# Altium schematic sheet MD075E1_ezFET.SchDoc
size 431 x 279 mm; Date: Not shown in title block; ApprovedBy: Not shown in title block; CheckedBy: Not shown in title block; Author: Not shown in title block; CompanyName: Not shown in title block; DrawnBy: Murugavel Raju; Engineer: Not shown in title block; Organization: Not shown in title block; Address1: Not shown in title block; Address2: Not shown in title block; Address3: Not shown in title block; Address4: Not shown in title block; DocumentNumber: 1; Revision: Use project parameter SCH_Rev; SheetNumber: 1; SheetTotal: 3; PageSetup: Record=PageOptions¦CenterHorizontal=True¦CenterVertical=True¦PrintScale=1.00¦XCorrection=1.00¦YCorrection=1.00¦PrintKind=0¦BorderSize=5000000¦LeftOffset=0¦BottomOffset=0¦Orientation=2¦PaperLength=1000¦PaperWidth=1000¦Scale=100¦PaperSource=15¦PrintQuality=600¦MediaType=1¦DitherType=10¦PaperKind=Letter¦PrintScaleMode=1
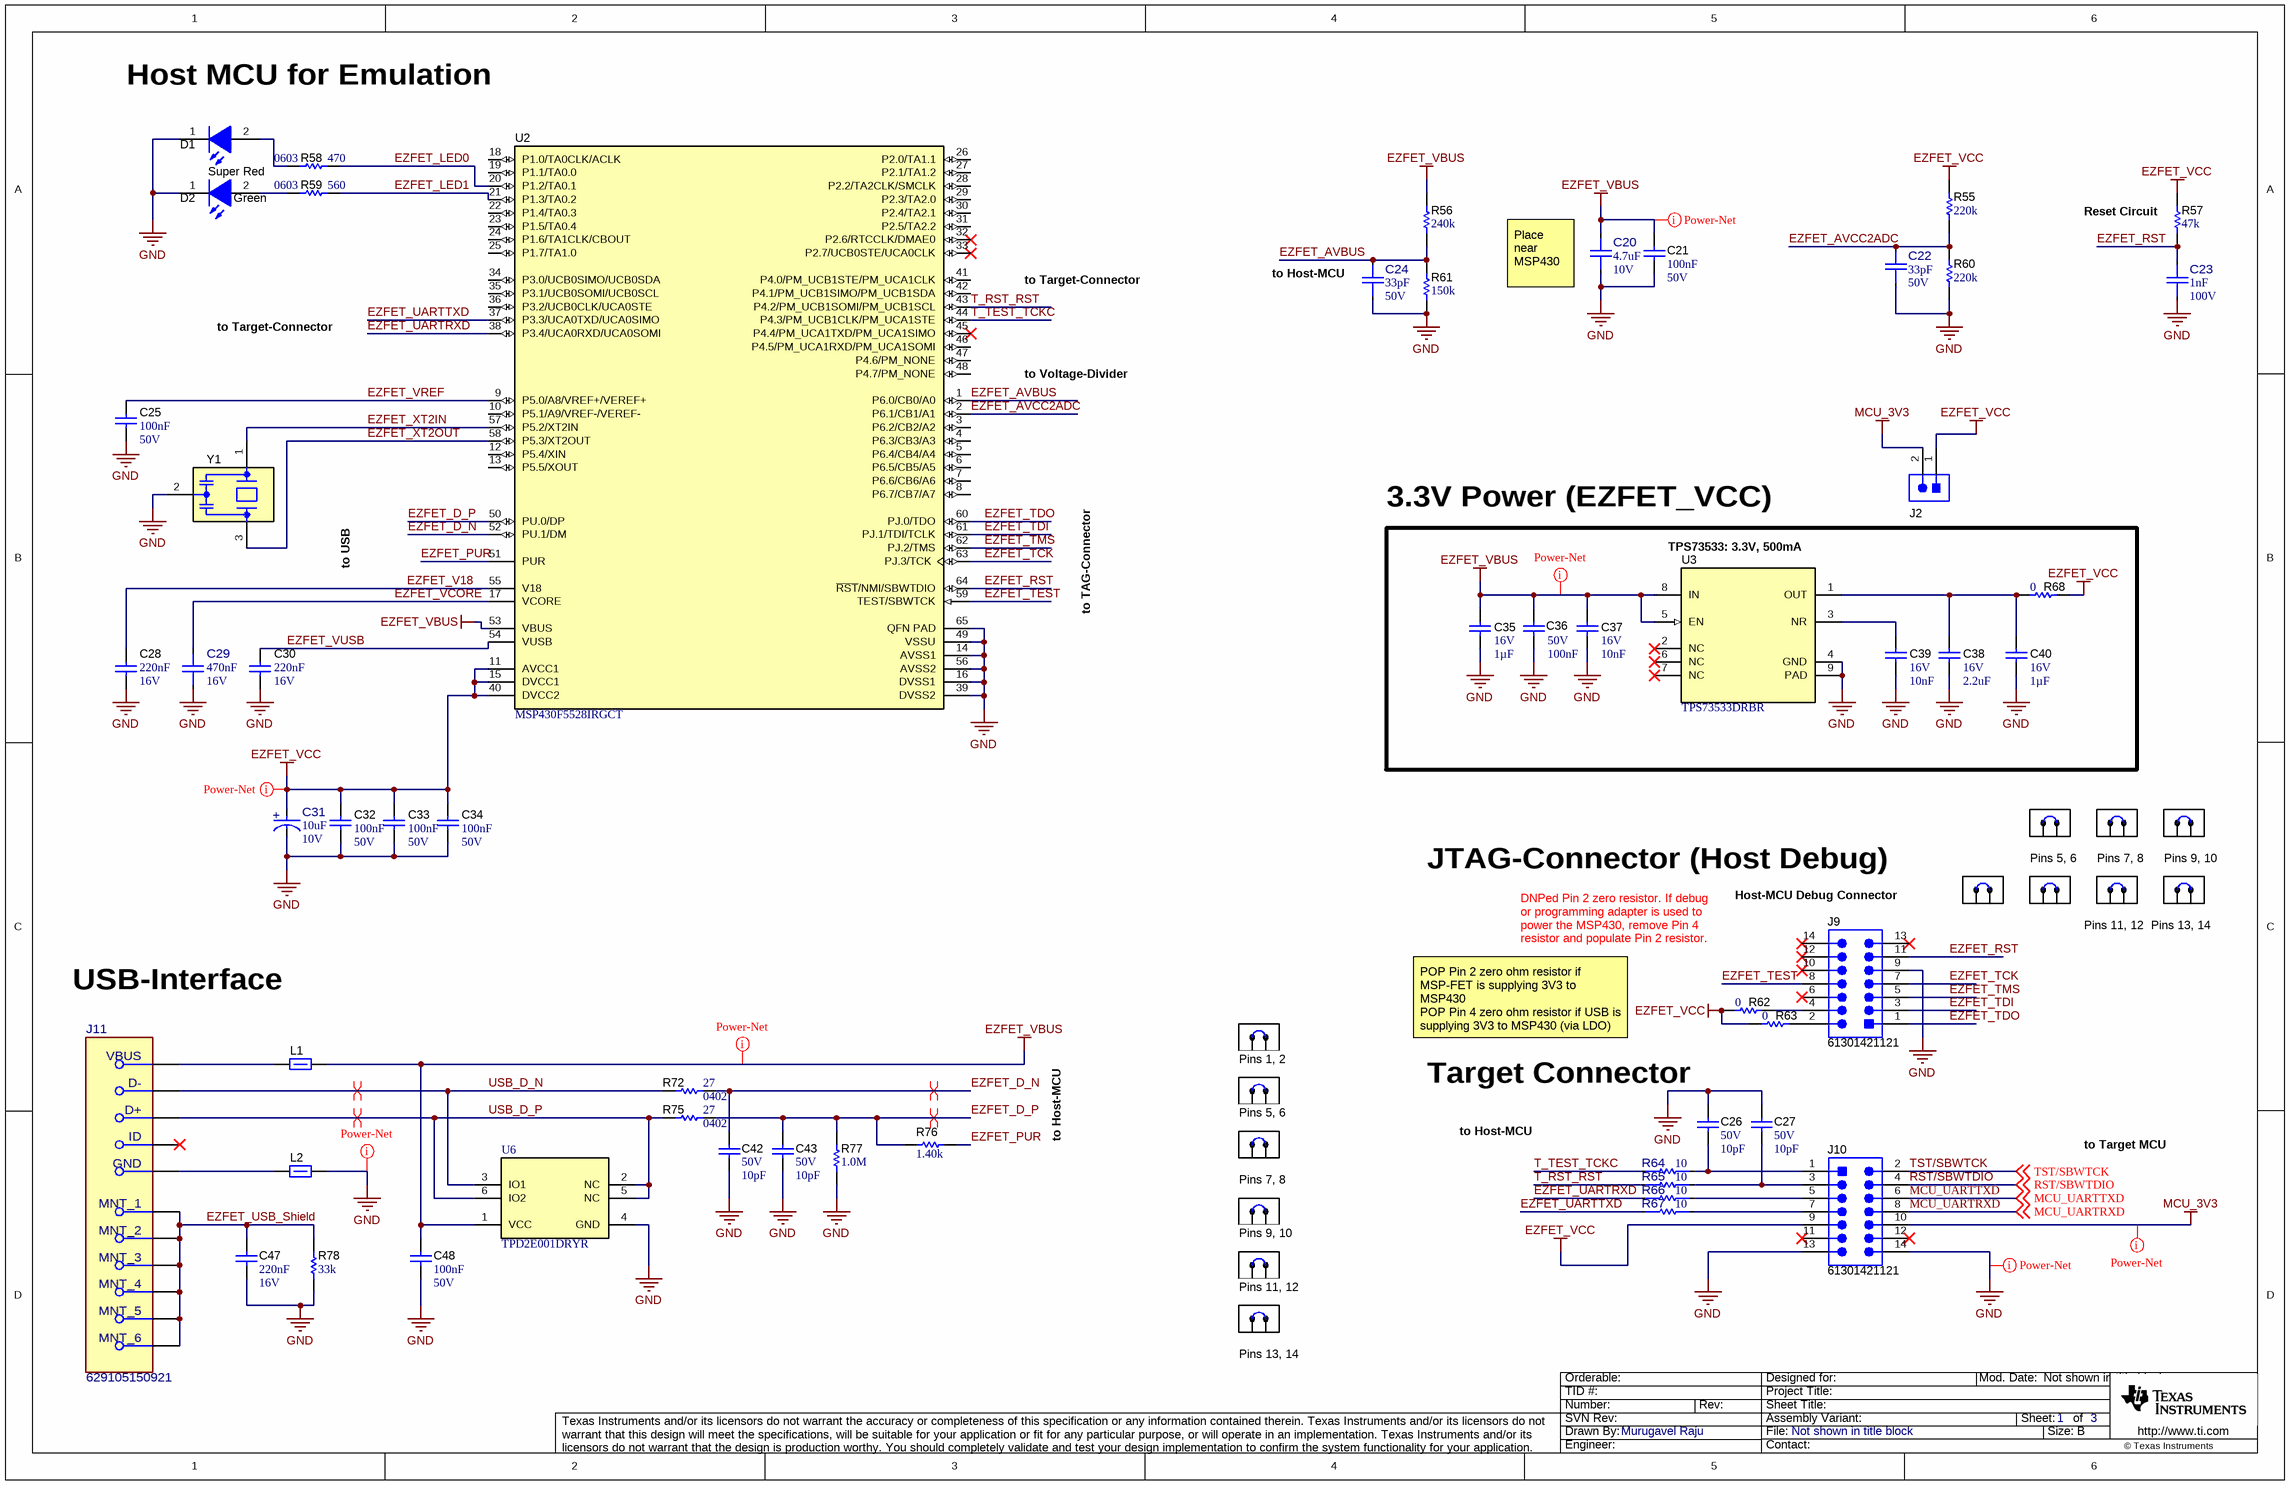
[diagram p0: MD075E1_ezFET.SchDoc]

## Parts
C20  ValueDisplayed: 4.7uF  VDC_V: 10V  [FP-885012106012_0603-MFG]  (hidden comment: 885012106012)
C21  Cap_F: 100nF  VDC_V: 50V  [0603]  (hidden comment: 885012206095)
C22  ValueDisplayed: 33pF  VDC_V: 50V  [FP-885012005058_0402-MFG]  (hidden comment: 885012005058)
C23  ValueDisplayed: 1nF  VDC_V: 100V  [FP-885012006085_0603-MFG]  (hidden comment: 885012006085)
C24  ValueDisplayed: 33pF  VDC_V: 50V  [FP-885012005058_0402-MFG]  (hidden comment: 885012005058)
C25  Cap_F: 100nF  VDC_V: 50V  [0603]  (hidden comment: 885012206095)
C26  VDC_V: 50V  ValueDisplayed: 10pF  [0402]  (hidden comment: 885012005055)
C27  VDC_V: 50V  ValueDisplayed: 10pF  [0402]  (hidden comment: 885012005055)
C28  Cap_F: 220nF  VDC_V: 16V  [0603L]  (hidden comment: 885012206048)
C29  VDC_V: 16V  Cap_F: 470nF  [FP-885012206050_0603-MFG]  (hidden comment: 885012206050)
C30  Cap_F: 220nF  VDC_V: 16V  [0603L]  (hidden comment: 885012206048)
C31  ValueDisplayed: 10uF  VDC_V: 10V  [FP-875105240001_SMT_CAP_4MM3_4MM3-MFG]  (hidden comment: 875105240001)
C32  Cap_F: 100nF  VDC_V: 50V  [0603]  (hidden comment: 885012206095)
C33  Cap_F: 100nF  VDC_V: 50V  [0603]  (hidden comment: 885012206095)
C34  Cap_F: 100nF  VDC_V: 50V  [0603]  (hidden comment: 885012206095)
C35  Cap_F: 1µF  VDC_V: 16V  [0603]  (hidden comment: 885012206052)
C36  Cap_F: 100nF  VDC_V: 50V  [0603]  (hidden comment: 885012206095)
C37  Cap_F: 10nF  VDC_V: 16V  [0603]  (hidden comment: 885012206040)
C38  VDC_V: 16V  ValueDisplayed: 2.2uF  [0603]  (hidden comment: 885012106018)
C39  Cap_F: 10nF  VDC_V: 16V  [0603]  (hidden comment: 885012206040)
C40  Cap_F: 1µF  VDC_V: 16V  [0603]  (hidden comment: 885012206052)
C42  VDC_V: 50V  ValueDisplayed: 10pF  [0402]  (hidden comment: 885012005055)
C43  VDC_V: 50V  ValueDisplayed: 10pF  [0402]  (hidden comment: 885012005055)
C47  Cap_F: 220nF  VDC_V: 16V  [0603L]  (hidden comment: 885012206048)
C48  Cap_F: 100nF  VDC_V: 50V  [0603]  (hidden comment: 885012206095)
D1  value Super Red  [WL-SMCW_RED]  (hidden comment: 150060SS75000)
D2  value Green  [WL-SMCW_GREEN]  (hidden comment: 150060VS75000)
J2  HTSW-102-07-G-S  [Samtec_HTSW-102-07-G-S]  (value not drawn)
J9  61301421121  [Wurth_61301421121]
J10  61301421121  [Wurth_61301421121]
J11  629105150921  [FP-629105150921_CONN_PTH_USB_8MM0_5MM6-MFG]
L1  742792621  [0603L]  (value not drawn)
L2  742792621  [0603L]  (value not drawn)
R55  ValueDisplayed: 220k  [0402]  (hidden comment: RC0402FR-07220KL)
R56  ValueDisplayed: 240k  [0402]  (hidden comment: CRCW0402240KFKED)
R57  ValueDisplayed: 47k  [0402]  (hidden comment: CRCW040247K0JNED)
R58  ValueDisplayed: 470  [0603]  (hidden comment: RC0603JR-07470RL)
R59  ValueDisplayed: 560  [0603]  (hidden comment: RC0603JR-07560RL)
R60  ValueDisplayed: 220k  [0402]  (hidden comment: RC0402FR-07220KL)
R61  ValueDisplayed: 150k  [0402]  (hidden comment: CRCW0402150KFKED)
R62  value 0  [0603L]  (hidden comment: Resistor)
R63  value 0  [0603L]  (hidden comment: Resistor)
R64  value 10  [FP-560050310009_0402-MFG]  (hidden comment: 560050310009)
R65  value 10  [FP-560050310009_0402-MFG]  (hidden comment: 560050310009)
R66  value 10  [FP-560050310009_0402-MFG]  (hidden comment: 560050310009)
R67  value 10  [FP-560050310009_0402-MFG]  (hidden comment: 560050310009)
R68  value 0  [0603L]  (hidden comment: Resistor)
R72  PackageReference: 0402  ValueDisplayed: 27  [0402L]  (hidden comment: CRCW040227R0JNED)
R75  PackageReference: 0402  ValueDisplayed: 27  [0402L]  (hidden comment: CRCW040227R0JNED)
R76  ValueDisplayed: 1.40k  [0402L]  (hidden comment: CRCW04021K40FKED)
R77  ValueDisplayed: 1.0M  [0402L]  (hidden comment: CRCW04021M00JNED)
R78  ValueDisplayed: 33k  [0402S]  (hidden comment: CRCW040233K0JNED)
SH-J22  60900213421  [Wurth_60900213421]  (value not drawn)
SH-J23  60900213421  [Wurth_60900213421]  (value not drawn)
SH-J24  60900213421  [Wurth_60900213421]  (value not drawn)
SH-J25  60900213421  [Wurth_60900213421]  (value not drawn)
SH-J26  60900213421  [Wurth_60900213421]  (value not drawn)
SH-J27  60900213421  [Wurth_60900213421]  (value not drawn)
SH-J28  60900213421  [Wurth_60900213421]  (value not drawn)
SH-J29  60900213421  [Wurth_60900213421]  (value not drawn)
SH-J31  60900213421  [Wurth_60900213421]  (value not drawn)
SH-J32  60900213421  [Wurth_60900213421]  (value not drawn)
SH-J33  60900213421  [Wurth_60900213421]  (value not drawn)
SH-J34  60900213421  [Wurth_60900213421]  (value not drawn)
SH-J35  60900213421  [Wurth_60900213421]  (value not drawn)
U2  MSP430F5528IRGCT  [RGC0064B]
U3  TPS73533DRBR  [DRB0008A]
U6  TPD2E001DRYR  [DRY0006A]
Y1  CSTNR4M00GH5L000R0  [MuRata_CSTNR]  (value not drawn)

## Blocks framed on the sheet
3.3V Power (EZFET_VCC): C35-C40 R68 U3

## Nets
EZFET_VBUS: C20.2 C21.1 C35.1 C36.1 C37.1 C48.2 L1.2 R56.2 U2.53(VBUS) U3.5(EN) U3.8(IN) U6.1(VCC)
EZFET_VCC: C31.2(ANODE) C32.1 C33.1 C34.1 J2.1 J10.9 R55.2 R57.2 R62.2 R63.2 R68.1 U2.11(AVCC1) U2.15(DVCC1) U2.40(DVCC2)
GND: C20.1 C21.2 C22.1 C23.1 C24.1 C25.2 C26.1 C27.1 C28.2 C29.1 C30.2 C31.1(CATHODE) C32.2 C33.2 C34.2 C35.2 C36.2 C37.2 C38.2 C39.2 C40.2 C42.2 C43.2 C47.2 C48.1 D1.1(K) D2.1(K) J9.9 J10.13 J10.14 L2.2 R60.1 R61.1 R77.1 R78.1 U2.14(AVSS1) U2.16(DVSS1) U2.39(DVSS2) U2.49(VSSU) U2.56(AVSS2) U2.65(QFN_PAD) U3.4(GND) U3.9(PAD) U6.4(GND) Y1.2(GND)
MCU_3V3: J2.2 J10.10
EZFET_AVBUS: C24.2 R56.1 R61.2 U2.1(P6.0/CB0/A0)
EZFET_AVCC2ADC: C22.2 R55.1 R60.2 U2.2(P6.1/CB1/A1)
EZFET_D_N: C42.1 R72.2 U2.52(PU.1/DM)
EZFET_D_P: C43.1 R75.2 R76.1 R77.2 U2.50(PU.0/DP)
EZFET_LED0: R58.1 U2.20(P1.2/TA0.1)
EZFET_LED1: R59.1 U2.21(P1.3/TA0.2)
EZFET_PUR: R76.2 U2.51(PUR)
EZFET_RST: C23.2 J9.11 R57.1 U2.64(~{RST}/NMI/SBWTDIO)
EZFET_TCK: J9.7 U2.63(PJ.3/TCK)
EZFET_TDI: J9.3 U2.61(PJ.1/TDI/TCLK)
EZFET_TDO: J9.1 U2.60(PJ.0/TDO)
EZFET_TEST: J9.8 U2.59(TEST/SBWTCK)
EZFET_TMS: J9.5 U2.62(PJ.2/TMS)
EZFET_UARTRXD: R66.1 U2.38(P3.4/UCA0RXD/UCA0SOMI)
EZFET_UARTTXD: R67.1 U2.37(P3.3/UCA0TXD/UCA0SIMO)
EZFET_USB_Shield: C47.1 J11.6(MNT_1) J11.7(MNT_2) J11.8(MNT_3) J11.9(MNT_4) J11.10(MNT_5) J11.11(MNT_6) R78.2
EZFET_V18: C28.1 U2.55(V18)
EZFET_VCORE: C29.2 U2.17(VCORE)
EZFET_VREF: C25.1 U2.9(P5.0/A8/VREF+/VEREF+)
EZFET_VUSB: C30.1 U2.54(VUSB)
EZFET_XT2IN: U2.57(P5.2/XT2IN) Y1.1(In)
EZFET_XT2OUT: U2.58(P5.3/XT2OUT) Y1.3(Out)
MCU_UARTRXD: J10.8 ; off-sheet MCU_UARTRXD
MCU_UARTTXD: J10.6 ; off-sheet MCU_UARTTXD
RST/SBWTDIO: J10.4 ; off-sheet RST/SBWTDIO
T_RST_RST: R65.1 U2.43(P4.2/PM_UCB1SOMI/PM_UCB1SCL)
T_TEST_TCKC: R64.1 U2.44(P4.3/PM_UCB1CLK/PM_UCA1STE)
TST/SBWTCK: J10.2 ; off-sheet TST/SBWTCK
USB_D_N: J11.2(D-) R72.1 U6.3(IO1)
USB_D_P: J11.3(D+) R75.1 U6.2(NC) U6.5(NC) U6.6(IO2)
NetC26_2: C26.2 J10.1 R64.2
NetC27_2: C27.2 J10.3 R65.2
NetC38_1: C38.1 C40.1 R68.2 U3.1(OUT)
NetC39_1: C39.1 U3.3(NR)
NetD1_2: D1.2(A) R58.2
NetD2_2: D2.2(A) R59.2
NetJ9_2: J9.2 R63.1
NetJ9_4: J9.4 R62.1
NetJ10_5: J10.5 R66.2
NetJ10_7: J10.7 R67.2
NetJ11_1: J11.1(VBUS) L1.1
NetJ11_5: J11.5(GND) L2.1

Not connected (* = marked no-connect by the designer): J9 6* 10* 12* 13* 14*; J10 11* 12*; J11 4(ID)*; U2 3(P6.2/CB2/A2) 4(P6.3/CB3/A3) 5(P6.4/CB4/A4) 6(P6.5/CB5/A5) 7(P6.6/CB6/A6) 8(P6.7/CB7/A7) 10(P5.1/A9/VREF-/VEREF-) 12(P5.4/XIN) 13(P5.5/XOUT) 18(P1.0/TA0CLK/ACLK) 19(P1.1/TA0.0) 22(P1.4/TA0.3) 23(P1.5/TA0.4) 24(P1.6/TA1CLK/CBOUT) 25(P1.7/TA1.0) 26(P2.0/TA1.1) 27(P2.1/TA1.2) 28(P2.2/TA2CLK/SMCLK) 29(P2.3/TA2.0) 30(P2.4/TA2.1) 31(P2.5/TA2.2) 32(P2.6/RTCCLK/DMAE0)* 33(P2.7/UCB0STE/UCA0CLK)* 34(P3.0/UCB0SIMO/UCB0SDA) 35(P3.1/UCB0SOMI/UCB0SCL) 36(P3.2/UCB0CLK/UCA0STE) 41(P4.0/PM_UCB1STE/PM_UCA1CLK) 42(P4.1/PM_UCB1SIMO/PM_UCB1SDA) 45(P4.4/PM_UCA1TXD/PM_UCA1SIMO)* 46(P4.5/PM_UCA1RXD/PM_UCA1SOMI) 47(P4.6/PM_NONE) 48(P4.7/PM_NONE); U3 2(NC)* 6(NC)* 7(NC)*

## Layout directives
net class Power-Net: EZFET_VBUS, EZFET_VCC, GND, MCU_3V3
differential pair: EZFET_D_N, EZFET_D_P, USB_D_N, USB_D_P

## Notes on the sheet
- Host MCU for Emulation
- (near R57) Reset Circuit
- to Target-Connector
- (near C24) to Host-MCU
- (near C20) Place near MSP430
- to Voltage-Divider
- to USB
- to TAG-Connector
- (near U3) TPS73533: 3.3V, 500mA
- JTAG-Connector (Host Debug)
- (near J9) Host-MCU Debug Connector
- (near SH-J23) Pins 5, 6
- (near SH-J27) Pins 7, 8
- (near SH-J28) Pins 9, 10
- DNPed Pin 2 zero resistor. If debug or programming adapter is used to power the MSP430, remove Pin 4 resistor and populate Pin 2 resistor.
- Pins 11, 12
- Pins 13, 14
- USB-Interface
- POP Pin 2 zero ohm resistor if MSP-FET is supplying 3V3 to MSP430
  POP Pin 4 zero ohm resistor if USB is supplying 3V3 to MSP430 (via LDO)
- to Host-MCU
- (near SH-J29) Pins 1, 2
- Target Connector
- (near SH-J31) Pins 5, 6
- to Target MCU
- Pins 7, 8
- (near SH-J33) Pins 9, 10
- (near SH-J34) Pins 11, 12
- (near SH-J35) Pins 13, 14

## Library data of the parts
C20 = CMP-0097305-1: 4.7 µF ±20% 10V Ceramic Capacitor X5R 0603 (1608 Metric); Manufacturer: Wurth Electronics; Cap_F: 4.7µF; Value: 4.7µF; AEC Qualified: No; SizeZ_mm: 0.87mm; TempCo: 15%
C21 C25 C32-C34 C36 C48 = CMP-0006837-4: CAP, CERM, 0.1 uF, 50 V, +/- 10%, X7R, 0603; Manufacturer: Wurth Elektronik; TaMin_C: -55°C; Polarized: N; SizeAreaWB_mm2: 4.68; Value1: Unknown; U/M: EA; Value: 0.1uF; TaMax_C: 125°C; SizeZ_mm: 1; SizeX_mm: 1.6; SizeY_mm: 0.8; SizeArea_mm2: 1.28; AEC Category: Q200
C22 C24 = CMP-0097306-1: 33 pF ±5% 50V Ceramic Capacitor C0G, NP0 0402 (1005 Metric); Manufacturer: Wurth Electronics; AEC Qualified: No; Value: 33pF; TempCo: 30ppm/°C; SizeZ_mm: 0.55mm
C23 = CMP-0097311-1: 1000 pF ±5% 100V Ceramic Capacitor C0G, NP0 0603 (1608 Metric); Manufacturer: Wurth Electronics; TempCo: 30ppm/°C; SizeZ_mm: 0.87mm; AEC Qualified: No; Value: 1nF
C26 C27 C42 C43 = CMP-0006215-2: CAP, CERM, 10 pF, 50 V, +/- 5%, C0G/NP0, 0402; Manufacturer: Wurth Elektronik; TaMin_C: -55°C; Polarized: N; SizeAreaWB_mm2: 3; Value1: Unknown; U/M: EA; Value: 10pF; TaMax_C: 125°C; SizeZ_mm: 0.6; SizeX_mm: 1; SizeY_mm: 0.5; AEC Category: Q200
C28 C30 C47 = CMP-0006830-4: CAP, CERM, 0.22 uF, 16 V, +/- 10%, X7R, 0603; Manufacturer: Wurth Elektronik; TaMin_C: -55°C; Polarized: N; SizeAreaWB_mm2: 4.68; Value1: Unknown; U/M: EA; Value: 0.22uF; TaMax_C: 125°C; SizeZ_mm: 1; SizeX_mm: 1.6; SizeY_mm: 0.8; Cap_Case: 0603; SizeArea_mm2: 1.28; AEC Category: Q200
C29 = CMP-0097608-1: 0.47 µF ±10% 16V Ceramic Capacitor X7R 0603 (1608 Metric); Manufacturer: Wurth Electronics; AEC Qualified: No; Value: 470nF; TempCo: 15%; SizeZ_mm: 0.87mm
C31 = CMP-0097340-1: Alum. Polymer Cap 10µF 10V 5.5mmV-Chip WCAP-PSLP Series Lifetime 2000h +105°C; Manufacturer: Wurth Electronics; Life: 2000Hours; Dissipation Factor: 8%; Esr: 45m; IRMS_A: 1.2A; Tolerance_%: 20%; AEC Qualified: No; SizeZ_mm: 5.5mm; Leakage Current: 300uA
C35 C40 = CMP-0006831-4: CAP, CERM, 1 uF, 16 V, +/- 10%, X7R, 0603; Manufacturer: Wurth Elektronik; TaMin_C: -55°C; Polarized: N; SizeAreaWB_mm2: 4.68; Value1: Unknown; U/M: EA; Value: 1uF; TaMax_C: 125°C; SizeZ_mm: 1; SizeX_mm: 1.6; SizeY_mm: 0.8; SizeArea_mm2: 1.28; AEC Category: Q200
C37 C39 = CMP-0006828-4: CAP, CERM, 0.01 uF, 16 V, +/- 10%, X7R, 0603; Manufacturer: Wurth Elektronik; TaMin_C: -55°C; Polarized: N; SizeAreaWB_mm2: 4.68; Value1: Unknown; U/M: EA; Value: 0.01uF; TaMax_C: 125°C; SizeZ_mm: 1; SizeX_mm: 1.6; SizeY_mm: 0.8; SizeArea_mm2: 1.28; AEC Category: Q200
C38 = CMP-0006825-5: CAP, CERM, 2.2 uF, 16 V, +/- 20%, X5R, 0603; Manufacturer: Wurth Elektronik; TaMin_C: -55°C; Polarized: N; SizeAreaWB_mm2: 4.68; Value1: Unknown; U/M: EA; Value: 2.2uF; TaMax_C: 85°C; SizeZ_mm: 1; SizeX_mm: 1.6; SizeY_mm: 0.8; SizeArea_mm2: 1.28; Cap_F: 2.2µF; AEC Category: Q200
D1 = CMP-0002893-1: LED, Super Red, SMD; Manufacturer: Wurth Elektronik; Io_A: 20mA; Value1: W; U/M: EA; Vf_V: 1.9V; Type: AlInGaP
D2 = CMP-0002894-2: LED, Green, SMD; Manufacturer: Wurth Elektronik; Type: AlInGaP; Vf_V: 2V; Io_A: 20mA; Value1: W
J2 = CMP-0075483-1: Header, 100mil, 2x1, Gold, TH; Manufacturer: Samtec; Green_REACh: Passed; CT: False; Green_Lifecycle: Active; CNHeader: True
J9 J10 = CMP-0086014-1: Header, 2.54mm, 7x2, Gold, TH; Manufacturer: Wurth Elektronik; Pitch_mm: 2.54; Voltage_V: 250V; Shrouded: N; Gender: Male; Current_A: 3A; Cert_UL: Y; Row_Count: 2
J11 = CMP-0097752-1: Conn Micro USB 2.0 Type AB RCP 5 POS 0.65mm Solder RA SMD 5 Terminal 1 Port T/R; Manufacturer: Wurth Electronics; Shrouded: true; Voltage_V: 30V; Usb Standard: USB 2.0; Current_A: 1A; ContactFinish: Gold; SizeZ_mm: 3.2mm; Is Female: yes; Conn Orientation: Horizontal; AEC Qualified: No
L1 L2 = CMP-0003184-2: Ferrite Bead, 140 ohm @ 100 MHz, 0.55 A, 0603; Manufacturer: Wurth Elektronik; Ztyp@1GHz_Ohm: 271.401; ZTyp@100MHz_Ohm: 140; SizeAreaWB_mm2: 4.68; DCR_ohm: 0.2; Value1: 0.2 ohm; Value: 140 ohm; Imax_A: 550mA; SizeZ_mm: 1; SizeX_mm: 1.6; SizeY_mm: 0.8; Value2: 0.55A; SizeArea_mm2: 1.28
R55 R60 = CMP-0026728-1: RES, 220 k, 1%, 0.0625 W, 0402; Manufacturer: Yageo America; Power_W: 62.5mW; TempCo: 100 ppm/C; U/M: EA; Value: 220k; SizeX_mm: 1; SizeY_mm: 0.5; SizeZ_mm: 0.6; AEC Qualified: N; VDC_V: 50V; AEC Category: Q200
R56 = CMP-0026190-2: RES, 240 k, 1%, 0.063 W, AEC-Q200 Grade 0, 0402; Manufacturer: Vishay-Dale; Power_W: 63mW; TempCo: 100 ppm/C; Value: 240k; SizeX_mm: 1; SizeY_mm: 0.5; SizeZ_mm: 0.6; Value2: 0.063W; AEC Qualified: Y; VDC_V: 50V; AEC Category: Q200; AEC Grade: 0
R57 = CMP-0026935-3: RES, 47 k, 5%, 0.063 W, AEC-Q200 Grade 0, 0402; Manufacturer: Vishay-Dale; Power_W: 63mW; TempCo: 200 ppm/C; Value_Code: 47k0; Value: 47k; EIA_Code: E24; SizeX_mm: 1; SizeY_mm: 0.5; SizeZ_mm: 0.6; Value2: 0.063W; AEC Qualified: Y; VDC_V: 50V; AEC Category: Q200; AEC Grade: 0
R58 = CMP-0025924-5: RES, 470, 5%, 0.1 W, 0603; Manufacturer: Yageo; Power_W: 100mW; TempCo: 100 ppm/C; Value_Code: 470R; Value: 470; EIA_Code: E24; SizeX_mm: 1.6; SizeY_mm: 0.8; SizeZ_mm: 1; Value2: 0.1W; SizeArea_mm2: 1.28; AEC Qualified: N; VDC_V: 75V; AEC Category: Q200; SizeAreaWB_mm2: 4.68
R59 = CMP-0025930-5: RES, 560, 5%, 0.1 W, 0603; Manufacturer: Yageo; Power_W: 100mW; TempCo: 100 ppm/C; Value_Code: 560R; Value: 560; EIA_Code: E24; SizeX_mm: 1.6; SizeY_mm: 0.8; SizeZ_mm: 1; Value2: 0.1W; SizeArea_mm2: 1.28; AEC Qualified: N; VDC_V: 75V; AEC Category: Q200; SizeAreaWB_mm2: 4.68
R61 = CMP-0026021-3: RES, 150 k, 1%, 0.063 W, AEC-Q200 Grade 0, 0402; Manufacturer: Vishay-Dale; Power_W: 63mW; TempCo: 100 ppm/C; Value: 150k; EIA_Code: E96; SizeX_mm: 1; SizeY_mm: 0.5; SizeZ_mm: 0.6; Value2: 0.063W; AEC Qualified: Y; VDC_V: 50V; AEC Category: Q200; AEC Grade: 0
R62 R63 R68 = CMP-0025697-4: RES, 0, 5%, 0.1 W, AEC-Q200 Grade 0, 0603; PartNumber: CRCW06030000Z0EA; Manufacturer: Vishay-Dale; Value_Code: 0000; Power_W: 100mW; Value2: 0.1W; VDC_V: 75V; TempCo: 200 ppm/C; EIA_Code: E24; AEC Category: Q200; AEC Qualified: Y; SizeArea_mm2: 1.28; SizeX_mm: 1.6; SizeY_mm: 0.8; SizeZ_mm: 1
R64-R67 = CMP-0097401-1: Thick Film Resistors 0402 10Ω ±1% 0.125W; Manufacturer: Wurth Electronics; TempCo: 100ppm/°C; VDC_V: 1.118V; Power_W: 125mW; AEC Qualified: No; SizeZ_mm: 0.4mm
R72 R75 = CMP-0026888-3: RES, 27, 5%, 0.063 W, AEC-Q200 Grade 0, 0402; Manufacturer: Vishay-Dale; Power_W: 63mW; TempCo: 200 ppm/C; Value_Code: 27R0; Value: 27; EIA_Code: E24; SizeX_mm: 1; SizeY_mm: 0.5; SizeZ_mm: 0.6; Value2: 0.063W; AEC Qualified: Y; VDC_V: 50V; AEC Category: Q200; AEC Grade: 0
R76 = CMP-0026085-3: RES, 1.40 k, 1%, 0.063 W, AEC-Q200 Grade 0, 0402; Manufacturer: Vishay-Dale; Power_W: 63mW; TempCo: 100 ppm/C; Value_Code: 1k40; Value: 1.40k; EIA_Code: E96; Res_ohm: 1.4k; SizeX_mm: 1; SizeY_mm: 0.5; SizeZ_mm: 0.6; Value2: 0.063W; AEC Qualified: Y; VDC_V: 50V; AEC Category: Q200; AEC Grade: 0
R77 = CMP-0026859-2: RES, 1.0 M, 5%, 0.063 W, AEC-Q200 Grade 0, 0402; Manufacturer: Vishay-Dale; Power_W: 63mW; TempCo: 200 ppm/C; Value_Code: 1M00; Value: 1.0Meg; EIA_Code: E24; Res_ohm: 1M; SizeX_mm: 1; SizeY_mm: 0.5; SizeZ_mm: 0.6; Value2: 0.063W; AEC Qualified: Y; VDC_V: 50V; AEC Category: Q200; AEC Grade: 0
R78 = CMP-0026907-3: RES, 33 k, 5%, 0.063 W, AEC-Q200 Grade 0, 0402; Manufacturer: Vishay-Dale; Power_W: 63mW; TempCo: 200 ppm/C; Value_Code: 33k0; Value: 33k; EIA_Code: E24; SizeX_mm: 1; SizeY_mm: 0.5; SizeZ_mm: 0.6; Value2: 0.063W; AEC Qualified: Y; VDC_V: 50V; AEC Category: Q200; AEC Grade: 0
SH-J22-SH-J29 SH-J31-SH-J35 = CMP-0003761-2: Shunt, 2.54mm, Gold, Black; Manufacturer: Wurth Elektronik
U2 = CMP-0039269-4: 16-Bit Ultra-Low-Power Microcontroller, 128KB Flash, 8KB RAM, USB, 12Bit ADC, 2 USCIs, 32Bit HW MPY, RGC0064B (VQFN-64); Alternate Manufacturer: Texas Instruments; Alternate PartNumber: MSP430F5528IRGCR; ADC: 12-bit SAR; ADC Channels: 16; Brown Out Reset: Yes; DMA: 3; Flash(KB): 128; Frequency(MHz): 25; GPIO: 47; Multiplier: 32x32; SRAM(B): 8192; Timers - 16-bit: 4; USB: 1; USCI_A (UART/LIN/IrDA/SPI): 2; Rating: Catalog; SizeArea_mm2: 81.0; SizeZ_mm: 1.0; Green_REACh: Passed; AEC Qualified: N; AEC Category: Q200; CompType: IC; Green_Lifecycle: Active; SizeY_mm: 9.0; SizeAreaWB_mm2: 121.0
U3 = CMP-0036328-3: 500mA, Adjustable, Low Quiescent Current, Low-Noise, High-PSRR, Single-Output LDO Regulator, DRB0008A (VSON-8); Manufacturer: Texas Instruments; CompType: IC; Green_Lifecycle: Active; SizeZ_mm: 1.0; Iq(Typ)(mA): 0.04; SizeY_mm: 3.0; SizeAreaWB_mm2: 16.0; SizeArea_mm2: 9.0; AEC Category: Q200; Vout Adj(Max)(V): 3.3; AEC Qualified: N; Accuracy(%): 2; Vin(Max)(V): 6.5; Vdo(Typ)(mV): 280; Iout(Max)(A): 0.5; Green_REACh: Passed; Rating: Catalog; Vin(Min)(V): 2.7
U6 = CMP-0043099-3: Low-Capacitance 2-Channel +/-15kV ESD Protection Array for High-Speed Data Interfaces, DRY0006A (USON-6); Manufacturer: Texas Instruments; IO Leakage Current(nA): 1; IEC 61000-4-2 Air-Gap(+/- kV): 15; USB High Speed: TRUE; IO Capacitance(Typ)(pF): 1.5; Eco-Plan: Green (RoHS & no Sb/Br); Breakdown Voltage(Min)(V): 11; IEC 61000-4-2 Contact(+/- kV): 8; AEC Category: Q200; AEC Qualified: N; CompType: IC; SizeAreaWB_mm2: 4.9; SizeArea_mm2: 1.45; SizeX_mm: 1.0; SizeZ_mm: 0.6; Rating: Catalog
Y1 = CMP-0085483-1: Oscillator, 4 MHz, 700 ppm, 39 pF, SMD; Manufacturer: MuRata; SizeArea_mm2: 9; Load Capacitance: 39 pF; SizeZ_mm: 1.2; AEC Category: Q200; Frequency Tolerance: 700 ppm; SizeX_mm: 4.5; SizeAreaWB_mm2: 16.5; TaMax_C: 85°C; TaMin_C: -20°C; SizeY_mm: 2; AEC Qualified: N; Frequency_Fixed: 4MHz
